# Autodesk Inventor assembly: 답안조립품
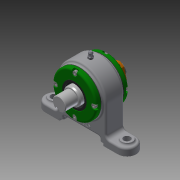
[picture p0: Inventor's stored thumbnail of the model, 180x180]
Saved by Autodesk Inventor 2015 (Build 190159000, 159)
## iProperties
Created: 2019-05
Part Number: 답안조립품
Document SubType Name: Assembly
Designer: now
Author: now
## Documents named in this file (13)
- C:\Users\now\Desktop\490504V1051\답안조립품.iam
- C:\Users\now\Desktop\490504V1051\개스킷.ipt
- C:\Users\now\Desktop\490504V1051\그리스니플 M6.ipt
- 그리스니플  M6.ipt
- C:\Users\now\Desktop\490504V1051\그리스니플개스킷.ipt
- C:\Users\now\Desktop\490504V1051\베어링너트.ipt
- C:\Users\now\Desktop\490504V1051\본체.ipt
- C:\Users\now\Desktop\490504V1051\볼트 M4.ipt
- C:\Users\now\Desktop\490504V1051\앵귤러 볼 베어링 7205.ipt
- C:\Users\now\Desktop\490504V1051\오일 실 28 40 5 B.ipt
- C:\Users\now\Desktop\490504V1051\축.ipt
- C:\Users\now\Desktop\490504V1051\칼라.ipt
- C:\Users\now\Desktop\490504V1051\커버.ipt
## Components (4 placed, 3 different names)
1. 개스킷:1
2. 그리스니플  M6:1
3. 그리스니플개스킷:1
4. 개스킷:2
